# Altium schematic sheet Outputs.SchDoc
size A4
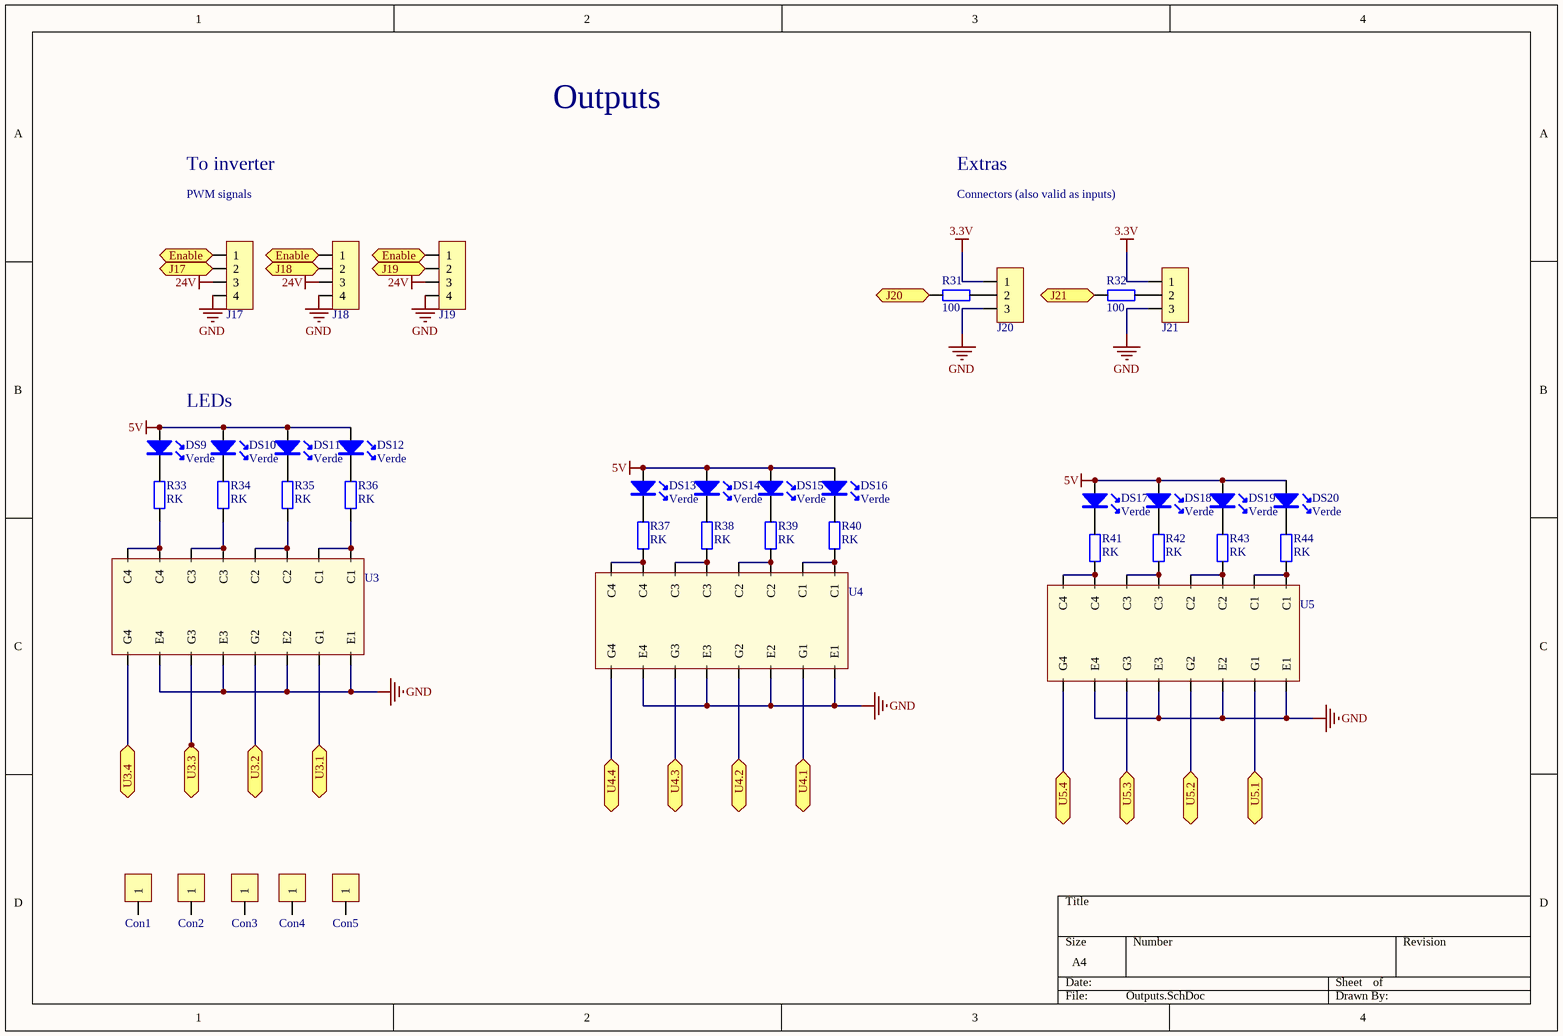
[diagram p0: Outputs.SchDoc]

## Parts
Con1  CON1  [Support]  (value not drawn)
Con2  CON1  [Support]  (value not drawn)
Con3  CON1  [Support]  (value not drawn)
Con4  CON1  [Support]  (value not drawn)
Con5  CON1  [Support]  (value not drawn)
DS9  Verde  [LED_100mil]
DS10  Verde  [LED_100mil]
DS11  Verde  [LED_100mil]
DS12  Verde  [LED_100mil]
DS13  Verde  [LED_100mil]
DS14  Verde  [LED_100mil]
DS15  Verde  [LED_100mil]
DS16  Verde  [LED_100mil]
DS17  Verde  [LED_100mil]
DS18  Verde  [LED_100mil]
DS19  Verde  [LED_100mil]
DS20  Verde  [LED_100mil]
J17  Cleva 2 vias  [Con4_KK_256]  (value not drawn)
J18  Cleva 2 vias  [Con4_KK_256]  (value not drawn)
J19  Cleva 2 vias  [Con4_KK_256]  (value not drawn)
J20  Cleva 2 vias  [Con3_KK_256]  (value not drawn)
J21  Cleva 2 vias  [Con3_KK_256]  (value not drawn)
R31  100  [1206]
R32  100  [1206]
R33  RK  [1206]
R34  RK  [1206]
R35  RK  [1206]
R36  RK  [1206]
R37  RK  [1206]
R38  RK  [1206]
R39  RK  [1206]
R40  RK  [1206]
R41  RK  [1206]
R42  RK  [1206]
R43  RK  [1206]
R44  RK  [1206]
U3  MMPQ3904  [SO-16]  (value not drawn)
U4  MMPQ3904  [SO-16]  (value not drawn)
U5  MMPQ3904  [SO-16]  (value not drawn)

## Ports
Enable, J17, J18, J19, J20, J21, U3.1, U3.2, U3.3, U3.4, U4.1, U4.2, U4.3, U4.4, U5.1, U5.2, U5.3, U5.4

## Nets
3.3V: J20.1 J21.1
5V: DS9.A DS10.A DS11.A DS12.A DS13.A DS14.A DS15.A DS16.A DS17.A DS18.A DS19.A DS20.A
24V: J17.3 J18.3 J19.3
GND: J17.4 J18.4 J19.4 J20.3 J21.3 U3.10(E4) U3.12(E3) U3.14(E2) U3.16(E1) U4.10(E4) U4.12(E3) U4.14(E2) U4.16(E1) U5.10(E4) U5.12(E3) U5.14(E2) U5.16(E1)
Enable: J17.1 J18.1 J19.1 ; port Enable
J17: J17.2 ; port J17
J18: J18.2 ; port J18
J19: J19.2 ; port J19
J20: R31.1 ; port J20
J21: R32.1 ; port J21
U3.1: U3.15(G1) ; port U3.1
U3.2: U3.13(G2) ; port U3.2
U3.3: U3.11(G3) ; port U3.3
U3.4: U3.9(G4) ; port U3.4
U4.1: U4.15(G1) ; port U4.1
U4.2: U4.13(G2) ; port U4.2
U4.3: U4.11(G3) ; port U4.3
U4.4: U4.9(G4) ; port U4.4
U5.1: U5.15(G1) ; port U5.1
U5.2: U5.13(G2) ; port U5.2
U5.3: U5.11(G3) ; port U5.3
U5.4: U5.9(G4) ; port U5.4
NetDS9_K: DS9.K R33.1
NetDS10_K: DS10.K R34.1
NetDS11_K: DS11.K R35.1
NetDS12_K: DS12.K R36.1
NetDS13_K: DS13.K R37.1
NetDS14_K: DS14.K R38.1
NetDS15_K: DS15.K R39.1
NetDS16_K: DS16.K R40.1
NetDS17_K: DS17.K R41.1
NetDS18_K: DS18.K R42.1
NetDS19_K: DS19.K R43.1
NetDS20_K: DS20.K R44.1
NetJ20_2: J20.2 R31.2
NetJ21_2: J21.2 R32.2
NetR33_2: R33.2 U3.7(C4) U3.8(C4)
NetR34_2: R34.2 U3.5(C3) U3.6(C3)
NetR35_2: R35.2 U3.3(C2) U3.4(C2)
NetR36_2: R36.2 U3.1(C1) U3.2(C1)
NetR37_2: R37.2 U4.7(C4) U4.8(C4)
NetR38_2: R38.2 U4.5(C3) U4.6(C3)
NetR39_2: R39.2 U4.3(C2) U4.4(C2)
NetR40_2: R40.2 U4.1(C1) U4.2(C1)
NetR41_2: R41.2 U5.7(C4) U5.8(C4)
NetR42_2: R42.2 U5.5(C3) U5.6(C3)
NetR43_2: R43.2 U5.3(C2) U5.4(C2)
NetR44_2: R44.2 U5.1(C1) U5.2(C1)

Not connected (* = marked no-connect by the designer): Con1 1; Con2 1; Con3 1; Con4 1; Con5 1

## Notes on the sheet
- Outputs
- To inverter
- Extras
- (near J17) PWM signals
- Connectors (also valid as inputs)
- LEDs

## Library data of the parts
DS9-DS20 = Led
J17-J19 = Con_4
J20 J21 = Con_3
R31-R44 = Resistencia: Potencia: 1/4W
